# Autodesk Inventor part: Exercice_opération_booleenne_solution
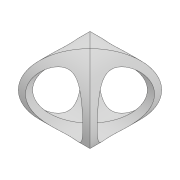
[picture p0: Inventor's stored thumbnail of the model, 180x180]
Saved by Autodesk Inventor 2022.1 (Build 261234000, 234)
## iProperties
Created: 2021-06
Part Number: Exercice_opération_booleenne_solution
Material: Générique
Document SubType Name: Modeling
Designer: Fabian
Density: 1 g/cm^3
Appearance: Par défaut
Mass: 11.4237 g
Surface Area: 82.2214 cm^2
Volume: 11.4237 cm^3
Author: Fabian
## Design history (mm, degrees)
sketch "Esquisse1"
  geometry: C1 r 25 at (0, 0); C2 r 20 at (0, 0); 1 further point
  constraints: 2 centre point, 1 coincident
  dimensions: "d0" = 50 diameter of C1; "d6" = 5 radial gap between concentric circles of C1 C2
sketch "Esquisse2"
  geometry: C1 r 25 at (0, 0); C2 r 20 at (0, 0); 1 further point
  constraints: 2 centre point, 1 coincident
  dimensions: "d1" = 50 diameter of C1; "d7" = 5 radial gap between concentric circles of C1 C2
extrude "Extrusion1" new body sketch "Esquisse1" stored distance "d2" = 50; taper "d3" = 0 deg
extrude "Extrusion2" new body sketch "Esquisse2" stored distance "d4" = 50; taper "d5" = 0 deg
feature "Combiner1"
  node "Solide3"
node "Solide1"
